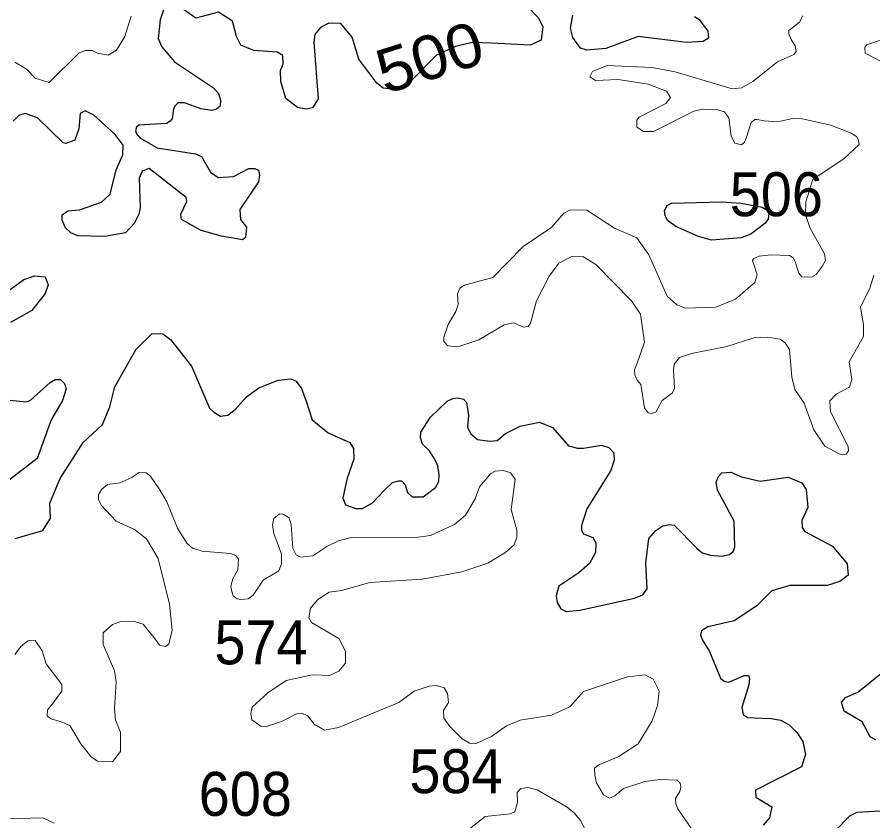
# Model space of a CAD drawing. Extents: x 499.9 to 555.3, y 9281.5 to 9336.8.
# Drawn here: x 550.375 to 553.489, y 9303.351 to 9306.276 of the extents above; entities that cross this region are included whole.
import ezdxf
from ezdxf.enums import TextEntityAlignment as Align

# ---------------------------------------------------------------- set-up
doc = ezdxf.new("R2010")
doc.units = 0
doc.header["$LTSCALE"] = 0.064
doc.layers.add('1', color=7, linetype='Continuous', lineweight=25)
doc.layers.add('2', color=7, linetype='Continuous', lineweight=13)
doc.layers.add('21', color=7, linetype='Continuous')
doc.layers.add('61', color=7, linetype='Continuous')

msp = doc.modelspace()

# ---------------------------------------------------------------- linework, layer by layer
at = {"layer": '1'}
for points in [[(552.1784, 9306.3699), (552.2718, 9306.2728), (552.2882, 9306.2409), (552.2815, 9306.1916), (552.2421, 9306.1739), (552.1015, 9306.1808), (552.0307, 9306.1836), (551.9705, 9306.1694), (551.9008, 9306.1377), (551.797, 9306.0317), (551.7497, 9306.0128), (551.7062, 9306.0175), (551.6841, 9306.0349), (551.6187, 9306.1233), (551.594, 9306.2032), (551.5529, 9306.2532), (551.5095, 9306.2535), (551.4789, 9306.2378), (551.4576, 9306.2122), (551.4546, 9306.1844), (551.4702, 9305.9784), (551.4498, 9305.9461), (551.4267, 9305.9403), (551.3948, 9305.9464), (551.3529, 9305.9801), (551.3347, 9306.041), (551.3336, 9306.0816), (551.3429, 9306.1057), (551.3417, 9306.1365), (551.3205, 9306.1487), (551.2365, 9306.1538), (551.1886, 9306.1734), (551.1729, 9306.2059), (551.1582, 9306.2611), (551.1079, 9306.294), (551.0249, 9306.2716), (550.9562, 9306.3202)], [(550.9088, 9306.306), (550.8955, 9306.2661), (550.888, 9306.1979), (550.9016, 9306.1675), (550.9476, 9306.1131), (551.0895, 9306.0185), (551.1075, 9305.9981), (551.1142, 9305.9738), (551.1136, 9305.9516), (551.1006, 9305.9406), (551.0835, 9305.9358), (551.0432, 9305.942), (550.9835, 9305.9637), (550.9606, 9305.9639), (550.9492, 9305.9531), (550.9437, 9305.9417), (550.9389, 9305.9074), (550.9318, 9305.8976), (550.9178, 9305.8893), (550.8176, 9305.8826), (550.8087, 9305.8758)], [(552.8404, 9306.2782), (552.8571, 9306.2672), (552.8888, 9306.2249), (552.8911, 9306.1998), (552.8715, 9306.1872), (552.8113, 9306.1837), (552.6345, 9306.2058), (552.5177, 9306.1614), (552.4485, 9306.1551), (552.4255, 9306.1632), (552.3967, 9306.2018), (552.389, 9306.2354), (552.3967, 9306.283)], [(551.024, 9305.7778), (551.0457, 9305.7688), (551.0786, 9305.7117), (551.1061, 9305.6922), (551.1623, 9305.6954), (551.2184, 9305.7247), (551.2394, 9305.7251), (551.2534, 9305.7183), (551.2573, 9305.7008), (551.2533, 9305.6768), (551.1857, 9305.5763), (551.1875, 9305.5392), (551.209, 9305.5118), (551.2057, 9305.4744), (551.1949, 9305.4648), (551.1188, 9305.4782), (551.044, 9305.4993), (550.9727, 9305.5393), (550.9704, 9305.5592), (550.9925, 9305.6051), (550.9895, 9305.62), (550.8553, 9305.7247), (550.8294, 9305.7153), (550.8189, 9305.6896), (550.8225, 9305.5836), (550.8173, 9305.5592), (550.8003, 9305.5248), (550.7689, 9305.4905), (550.6937, 9305.477), (550.5952, 9305.4804), (550.5695, 9305.4914), (550.5511, 9305.5086), (550.5391, 9305.5371), (550.5386, 9305.5568), (550.5586, 9305.5706), (550.6013, 9305.5742), (550.6817, 9305.6025), (550.7135, 9305.6321), (550.7352, 9305.7204), (550.7588, 9305.7751), (550.7602, 9305.8094), (550.732, 9305.8491), (550.6535, 9305.9185), (550.6221, 9305.9344), (550.6044, 9305.9252), (550.599, 9305.8693), (550.5843, 9305.828), (550.5525, 9305.8162), (550.5419, 9305.8182), (550.4485, 9305.9096), (550.4041, 9305.9252), (550.3804, 9305.9176), (550.3602, 9305.8975)], [(550.8087, 9305.8758), (550.8053, 9305.8626), (550.8087, 9305.8513), (550.8217, 9305.8365), (550.8849, 9305.8001), (551.024, 9305.7778)], [(550.3498, 9305.2846), (550.3994, 9305.3208), (550.4374, 9305.3346), (550.4769, 9305.3301), (550.488, 9305.3011), (550.4763, 9305.27), (550.4278, 9305.2081), (550.35, 9305.165)], [(550.3672, 9304.3789), (550.4687, 9304.4075), (550.4962, 9304.4522), (550.4936, 9304.5075), (550.5315, 9304.5968), (550.6153, 9304.7282), (550.6856, 9304.7927), (550.7125, 9304.8571), (550.7299, 9304.9298), (550.808, 9305.0671), (550.8665, 9305.125), (550.9048, 9305.1232), (550.9325, 9305.1028), (551.0092, 9305.005), (551.0751, 9304.8531), (551.0909, 9304.8378), (551.1142, 9304.8235), (551.141, 9304.8269), (551.1679, 9304.8484), (551.2089, 9304.8938)], [(550.3115, 9304.8849), (550.4082, 9304.8759), (550.423, 9304.882), (550.495, 9304.9467), (550.5134, 9304.957), (550.5328, 9304.9575), (550.5469, 9304.9425), (550.5533, 9304.923), (550.5392, 9304.8802), (550.498, 9304.8101), (550.4478, 9304.6696), (550.3148, 9304.567)], [(551.2089, 9304.8938), (551.2549, 9304.9265), (551.3244, 9304.955), (551.371, 9304.9589), (551.3897, 9304.9509), (551.41, 9304.9241)], [(551.41, 9304.9241), (551.427, 9304.8777), (551.4489, 9304.8097), (551.5071, 9304.7624), (551.5852, 9304.7274), (551.5994, 9304.7064), (551.6006, 9304.6668), (551.5757, 9304.5976), (551.5599, 9304.5269), (551.57, 9304.5012), (551.6073, 9304.4871), (551.6311, 9304.4872), (551.6677, 9304.5083), (551.7118, 9304.5548), (551.7411, 9304.5819), (551.7639, 9304.5887), (551.7733, 9304.5881), (551.787, 9304.5732), (551.7954, 9304.5461), (551.8129, 9304.53), (551.8523, 9304.5303), (551.8968, 9304.5636), (551.9095, 9304.5857), (551.911, 9304.6103), (551.9062, 9304.6445), (551.8898, 9304.6746), (551.874, 9304.6991), (551.8496, 9304.7211), (551.8428, 9304.7448), (551.8433, 9304.7655), (551.8786, 9304.8202), (551.9399, 9304.8785), (551.9609, 9304.8876), (551.9784, 9304.8903), (551.9989, 9304.8849), (552.0099, 9304.8728), (552.0178, 9304.826), (552.0134, 9304.7838), (552.0242, 9304.7599), (552.0499, 9304.7384), (552.0954, 9304.7329), (552.1222, 9304.7353), (552.1517, 9304.7606), (552.205, 9304.7873), (552.2758, 9304.8018), (552.3233, 9304.7828), (552.381, 9304.7151), (552.4136, 9304.7074), (552.4358, 9304.707), (552.5018, 9304.7175), (552.5277, 9304.7092), (552.5463, 9304.6907), (552.5476, 9304.6629), (552.5357, 9304.6255), (552.4478, 9304.4869), (552.4281, 9304.426), (552.4281, 9304.4084), (552.4357, 9304.3957), (552.4702, 9304.3823), (552.4811, 9304.3629), (552.479, 9304.3272), (552.4575, 9304.2871), (552.419, 9304.2531), (552.3458, 9304.2044), (552.3366, 9304.1696), (552.3398, 9304.1449), (552.3532, 9304.1227), (552.3727, 9304.1132), (552.4222, 9304.1179), (552.6217, 9304.1611), (552.6512, 9304.1736), (552.6673, 9304.1957), (552.6626, 9304.288), (552.6739, 9304.3786), (552.6992, 9304.4072), (552.7244, 9304.4243), (552.7493, 9304.4291), (552.766, 9304.4266), (552.8488, 9304.3427), (552.8679, 9304.3263), (552.8984, 9304.3181), (552.9398, 9304.3138), (552.9669, 9304.3206), (552.9807, 9304.331), (552.9871, 9304.3462), (552.984, 9304.4409), (552.9233, 9304.5538), (552.9192, 9304.5824), (552.9256, 9304.603), (552.9389, 9304.6173), (552.9719, 9304.6202), (553.0112, 9304.6032), (553.0786, 9304.5873), (553.1812, 9304.6013), (553.2305, 9304.5806)], [(553.2305, 9304.5806), (553.2457, 9304.5568), (553.2526, 9304.491), (553.2309, 9304.444), (553.2318, 9304.4186), (553.2416, 9304.4036)], [(553.2416, 9304.4036), (553.3426, 9304.3509), (553.3959, 9304.2863), (553.3986, 9304.2447), (553.369, 9304.2214), (553.323, 9304.207), (553.187, 9304.2068), (553.1214, 9304.1883), (553.0667, 9304.1337), (552.9847, 9304.0785), (552.8886, 9304.0571), (552.8649, 9304.0428), (552.8617, 9304.0268), (552.8684, 9304.0088), (552.8944, 9303.9669), (552.9348, 9303.8696), (552.9484, 9303.8595), (552.9621, 9303.856), (552.9758, 9303.8609), (553.0203, 9303.8797), (553.0366, 9303.8799), (553.04, 9303.8694), (553.0372, 9303.8457), (553.0122, 9303.763), (553.0172, 9303.7372), (553.0324, 9303.7272), (553.0575, 9303.7262), (553.1186, 9303.7234), (553.1536, 9303.7176), (553.1858, 9303.699), (553.2121, 9303.6728), (553.234, 9303.6394), (553.2432, 9303.5926), (553.2298, 9303.5476), (553.0623, 9303.4627), (553.0626, 9303.4368), (553.1217, 9303.4014), (553.1127, 9303.3619), (553.0892, 9303.3349)], [(553.5, 9303.6457), (553.4787, 9303.6571), (553.45, 9303.7116), (553.3843, 9303.7497), (553.3744, 9303.7827), (553.3888, 9303.7999), (553.4338, 9303.8193), (553.5214, 9303.8894)], [(553.3485, 9303.3108), (553.4057, 9303.3695), (553.4321, 9303.3824), (553.5172, 9303.3875)]]:
    msp.add_lwpolyline(points, dxfattribs=at)
msp.add_lwpolyline([(552.7724, 9305.5141), (552.7421, 9305.5354), (552.7327, 9305.5537), (552.7301, 9305.5726), (552.7405, 9305.59), (552.7558, 9305.5989), (552.9398, 9305.6036), (553.009, 9305.5991), (553.0856, 9305.584), (553.1041, 9305.5734), (553.1107, 9305.5594), (553.1084, 9305.5408), (553.0958, 9305.5247), (553.0448, 9305.4856), (553.0097, 9305.4727), (552.9021, 9305.4645), (552.8544, 9305.4773)], close=True, dxfattribs=at)
at = {"layer": '2'}
for points in [[(550.3666, 9306.1114), (550.4086, 9306.0864), (550.4408, 9306.0532), (550.4909, 9306.0374), (550.6005, 9306.1455), (550.6231, 9306.1546), (550.6477, 9306.1549), (550.6669, 9306.1451), (550.7065, 9306.1378), (550.7365, 9306.1551), (550.7669, 9306.2059), (550.7902, 9306.2792)], [(553.2333, 9306.2804), (553.2237, 9306.2582), (553.1975, 9306.2386), (553.1835, 9306.2273), (553.1829, 9306.2145), (553.1913, 9306.1949), (553.2066, 9306.1708), (553.2094, 9306.1503), (553.2012, 9306.1402), (553.1417, 9306.1134), (553.0524, 9306.042), (553.0121, 9306.0186), (552.9774, 9306.0154), (552.7699, 9306.0767), (552.6846, 9306.0929), (552.5217, 9306.1001), (552.469, 9306.0777), (552.4584, 9306.059), (552.479, 9306.0448), (552.5624, 9306.0492), (552.6713, 9306.0321), (552.7376, 9306.0062), (552.7526, 9305.9831), (552.7356, 9305.9609), (552.6384, 9305.912), (552.6302, 9305.9005)], [(553.514, 9306.1166), (553.4613, 9306.1447), (553.4593, 9306.1662), (553.4675, 9306.1754), (553.5442, 9306.2012)], [(552.8714, 9305.9414), (552.9195, 9305.9401), (552.9486, 9305.9306), (552.9651, 9305.9093), (552.9738, 9305.8426), (552.9862, 9305.8167), (553.0108, 9305.8115), (553.0221, 9305.821), (553.0284, 9305.8353), (553.0457, 9305.8923), (553.0593, 9305.9032), (553.0683, 9305.9037), (553.0928, 9305.8985), (553.1246, 9305.8956), (553.1531, 9305.8975), (553.1981, 9305.9065), (553.2313, 9305.9052), (553.3359, 9305.8828), (553.41, 9305.8539), (553.4291, 9305.842), (553.4369, 9305.8285), (553.4397, 9305.8117), (553.385, 9305.7619), (553.2702, 9305.6846), (553.2453, 9305.6035), (553.2438, 9305.5574), (553.2594, 9305.5104), (553.3132, 9305.4148), (553.3162, 9305.3905), (553.3042, 9305.3677), (553.2822, 9305.3387), (553.2658, 9305.3299), (553.2308, 9305.3305), (553.2191, 9305.3445), (553.205, 9305.3893), (553.199, 9305.3996), (553.186, 9305.4081), (553.1187, 9305.4105), (553.0755, 9305.4061), (553.0556, 9305.3975), (553.0515, 9305.3904), (553.0544, 9305.3791), (553.068, 9305.3385), (553.059, 9305.3106), (552.9893, 9305.2499), (552.9179, 9305.2207), (552.8066, 9305.2163), (552.775, 9305.2292), (552.7407, 9305.2606), (552.6739, 9305.411), (552.6295, 9305.4731), (552.5489, 9305.5075), (552.4481, 9305.5736), (552.3885, 9305.574), (552.3646, 9305.5622), (552.3203, 9305.512), (552.2167, 9305.4408), (552.106, 9305.328), (552.0028, 9305.3003), (551.9856, 9305.2892), (551.9769, 9305.2675), (551.9793, 9305.2299), (551.9715, 9305.2042), (551.9432, 9305.157), (551.9273, 9305.1111), (551.9276, 9305.0951), (551.9427, 9305.0797), (551.9788, 9305.0761), (552.0554, 9305.1011), (552.1469, 9305.1558), (552.1817, 9305.1632), (552.2171, 9305.1479), (552.234, 9305.1496), (552.2428, 9305.1616), (552.2646, 9305.2431), (552.3113, 9305.3328), (552.3459, 9305.38), (552.3904, 9305.4035), (552.4331, 9305.4052), (552.481, 9305.3761), (552.6101, 9305.2432), (552.6435, 9305.1944), (552.6577, 9305.0924), (552.6307, 9305.017), (552.6212, 9304.9919), (552.6231, 9304.9733), (552.6312, 9304.955), (552.6448, 9304.9388), (552.6577, 9304.8538), (552.6713, 9304.8358), (552.6848, 9304.8338), (552.6994, 9304.838), (552.7222, 9304.8804), (552.7598, 9304.908), (552.7675, 9304.9254)], [(552.6302, 9305.9005), (552.6296, 9305.8751), (552.6538, 9305.8591), (552.6903, 9305.8594), (552.8371, 9305.9334), (552.8714, 9305.9414)], [(552.9573, 9305.0767), (553.0557, 9305.1092), (553.1042, 9305.1108), (553.151, 9305.1043), (553.1701, 9305.0901), (553.1859, 9305.0662), (553.1942, 9304.966), (553.2048, 9304.9202), (553.2385, 9304.8705), (553.2741, 9304.7744), (553.3136, 9304.7147), (553.3663, 9304.6866), (553.3783, 9304.683), (553.3912, 9304.6849), (553.4003, 9304.6973), (553.3992, 9304.7129), (553.3344, 9304.8388), (553.3328, 9304.8793), (553.3555, 9304.9042), (553.4045, 9304.9294), (553.4119, 9304.9565), (553.4027, 9305.0211), (553.455, 9305.1132), (553.4551, 9305.1562), (553.4442, 9305.2206), (553.4782, 9305.289), (553.4928, 9305.3367)], [(552.7675, 9304.9254), (552.763, 9304.9913), (552.7661, 9305.0129), (552.7848, 9305.0366), (552.8289, 9305.0517), (552.9573, 9305.0767)], [(551.3367, 9304.3219), (551.3364, 9304.2859), (551.3267, 9304.2609), (551.2702, 9304.2272), (551.255, 9304.2047), (551.2331, 9304.1723), (551.2157, 9304.1585), (551.189, 9304.1561), (551.1757, 9304.1583), (551.1605, 9304.1695), (551.1558, 9304.1854), (551.1522, 9304.2054), (551.1595, 9304.2311), (551.1775, 9304.2641), (551.1798, 9304.3026), (551.1701, 9304.3165), (551.1502, 9304.3243), (551.0481, 9304.3321), (551.0127, 9304.3437), (550.9918, 9304.361), (550.958, 9304.4154), (550.9193, 9304.5115), (550.8911, 9304.5586), (550.8602, 9304.6056), (550.8443, 9304.6179), (550.818, 9304.6188), (550.7924, 9304.6), (550.7487, 9304.5813), (550.7041, 9304.5745), (550.6828, 9304.558), (550.6704, 9304.5386), (550.6706, 9304.5205), (550.6808, 9304.4999), (550.7352, 9304.441), (550.802, 9304.4105), (550.8458, 9304.3775), (550.8878, 9304.3055), (550.9291, 9304.1392), (550.9386, 9304.0448), (550.9268, 9303.9933), (550.9132, 9303.9847), (550.8925, 9303.9907), (550.8778, 9304.0102), (550.8336, 9304.0666), (550.7973, 9304.0774), (550.7518, 9304.0763), (550.7216, 9304.0655), (550.6877, 9304.0349), (550.6878, 9303.993), (550.7296, 9303.8971), (550.735, 9303.8565), (550.7291, 9303.7602), (550.7329, 9303.7174), (550.7509, 9303.6729), (550.7505, 9303.6031), (550.7222, 9303.5659), (550.6677, 9303.5676), (550.6429, 9303.5847), (550.6059, 9303.6307), (550.5662, 9303.6973), (550.5309, 9303.7124), (550.4986, 9303.7215), (550.4845, 9303.7317), (550.4853, 9303.7553), (550.4963, 9303.7669), (550.5372, 9303.8227), (550.5378, 9303.8472), (550.4807, 9303.922), (550.4659, 9303.9697), (550.4403, 9304.0068), (550.4136, 9304.0055), (550.389, 9303.9871), (550.3669, 9303.9562)], [(552.7871, 9303.4881), (552.7763, 9303.4983), (552.7138, 9303.5017), (552.6585, 9303.4939), (552.582, 9303.4685), (552.5501, 9303.4419), (552.5304, 9303.4338), (552.5085, 9303.4452), (552.4834, 9303.4885), (552.4767, 9303.517), (552.4764, 9303.5424), (552.4898, 9303.5533), (552.5615, 9303.5842), (552.6353, 9303.6309), (552.6859, 9303.7144), (552.7055, 9303.7701), (552.7115, 9303.8233), (552.6893, 9303.866), (552.6608, 9303.8818), (552.5965, 9303.8754), (552.4358, 9303.8219), (552.3861, 9303.7656), (552.3195, 9303.7356), (552.2053, 9303.7167), (552.1556, 9303.6962), (552.1007, 9303.6579), (552.0451, 9303.6324), (552.0206, 9303.6329), (551.9947, 9303.6495), (551.95, 9303.6936), (551.9271, 9303.7241), (551.9258, 9303.7524), (551.9445, 9303.782), (551.9411, 9303.8143), (551.9289, 9303.8352), (551.9009, 9303.8431), (551.874, 9303.8405), (551.82, 9303.823), (551.7641, 9303.7817), (551.5444, 9303.69), (551.4933, 9303.6807), (551.456, 9303.7024), (551.4321, 9303.7335), (551.4094, 9303.7424), (551.3916, 9303.7398), (551.3367, 9303.712), (551.282, 9303.6944), (551.2614, 9303.6949), (551.2291, 9303.7181), (551.2248, 9303.7415), (551.2299, 9303.7642), (551.2875, 9303.8169), (551.354, 9303.8618), (551.449, 9303.882), (551.512, 9303.8796), (551.5452, 9303.8955), (551.5693, 9303.9252), (551.5696, 9303.9685), (551.5455, 9304.0138), (551.4454, 9304.0732), (551.4368, 9304.0898), (551.4427, 9304.1247), (551.4685, 9304.1561), (551.5099, 9304.1825), (551.5556, 9304.1887), (551.6582, 9304.218), (551.8485, 9304.2307), (551.9933, 9304.2565), (552.0879, 9304.2881), (552.1501, 9304.3258), (552.1839, 9304.3556), (552.1932, 9304.383), (552.193, 9304.4091), (552.1725, 9304.4841), (552.1866, 9304.5937), (552.1704, 9304.6171), (552.1451, 9304.6256), (552.1143, 9304.6236), (552.0981, 9304.6146), (552.0568, 9304.5659), (552.0414, 9304.5228), (552.0067, 9304.4633), (551.9669, 9304.4297), (551.8792, 9304.3897), (551.8333, 9304.3836), (551.5907, 9304.3817), (551.5444, 9304.3694), (551.5018, 9304.3497), (551.4512, 9304.3154), (551.4062, 9304.3105), (551.3896, 9304.3189), (551.3784, 9304.3433), (551.3715, 9304.428), (551.3644, 9304.4533), (551.3427, 9304.4667)], [(551.3427, 9304.4667), (551.3292, 9304.468), (551.3088, 9304.4507), (551.3038, 9304.4278), (551.3085, 9304.397), (551.3367, 9304.3219)], [(552.7796, 9303.3945), (552.7713, 9303.4129), (552.7711, 9303.4326), (552.7863, 9303.4573), (552.7904, 9303.4739), (552.7871, 9303.4881)], [(551.9813, 9303.2897), (552.0779, 9303.366), (552.1687, 9303.3758), (552.1861, 9303.3831), (552.196, 9303.419), (552.195, 9303.4539), (552.2078, 9303.4682), (552.2333, 9303.4718), (552.2678, 9303.4634), (552.3769, 9303.4003), (552.4037, 9303.3785), (552.4252, 9303.3521), (552.4919, 9303.2206)], [(552.8326, 9303.317), (552.7796, 9303.3945)], [(550.2043, 9303.3539), (550.4677, 9303.3615), (550.5089, 9303.3424)]]:
    msp.add_lwpolyline(points, dxfattribs=at)

# ---------------------------------------------------------------- texts
at = {"layer": '21', "width": 0.95}
for s, p in [('506', (552.9682, 9305.5513)), ('574', (551.0926, 9303.9203)), ('584', (551.8022, 9303.4514)), ('608', (551.0356, 9303.369))]:
    msp.add_text(s, height=0.16, dxfattribs=at).set_placement(p)
at = {"layer": '61', "width": 1.1}
msp.add_text('500', height=0.16, rotation=17.571, dxfattribs=at).set_placement((551.9003, 9306.0536), align=Align.CENTER)

doc.saveas('drawing.dxf')
